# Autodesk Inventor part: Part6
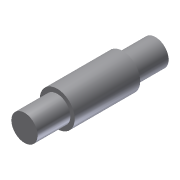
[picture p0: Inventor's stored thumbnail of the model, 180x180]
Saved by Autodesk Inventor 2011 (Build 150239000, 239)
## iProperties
Shininess: 77.0
Length Units: 11269
Angle Units: 11279
Time Units: 11290
Mass Units: 11283
Length Display Precision: 3
Angle Display Precision: 2
Created: 2002-01
Part Number: Part6
Document SubType Name: Modeling
Designer: ***
Density: 1 g/cm^3
Density: 0.0
Volumn: 0.0
Area: 0.0
PropertySet Name: Model Information
Control State: 0
Master: False
Checked Out: False
Author: ***
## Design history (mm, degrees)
sketch "Sketch1"
  geometry: L1 (1.545, 32.521)-(-4.455, 32.521); L2 (-4.455, 32.521)-(-4.455, 17.521); L3 (-4.455, 17.521)-(-6.455, 17.521); L4 (-6.455, 17.521)-(-6.455, -12.479); L5 (-6.455, -12.479)-(-4.455, -12.479); L6 (-4.455, -12.479)-(-4.455, -27.479); L7 (-4.455, -27.479)-(1.545, -27.479); L8 (1.545, -27.479)-(1.545, 32.521)
  constraints: 16 end point, 5 parallel, 2 equal length, 1 collinear, 1 horizontal, 1 perpendicular
  dimensions: "d0" = 16 diameter of L4 L8; "d1" = 12 diameter of L2 L8; "d2" = 60 distance of L7.end L1.start; "d3" = 30 distance of L3.end L4.end
revolve "Revolution1" sketch "Sketch1" stored, may be unused: angle "d4" = 90 deg
body "Solid1"
